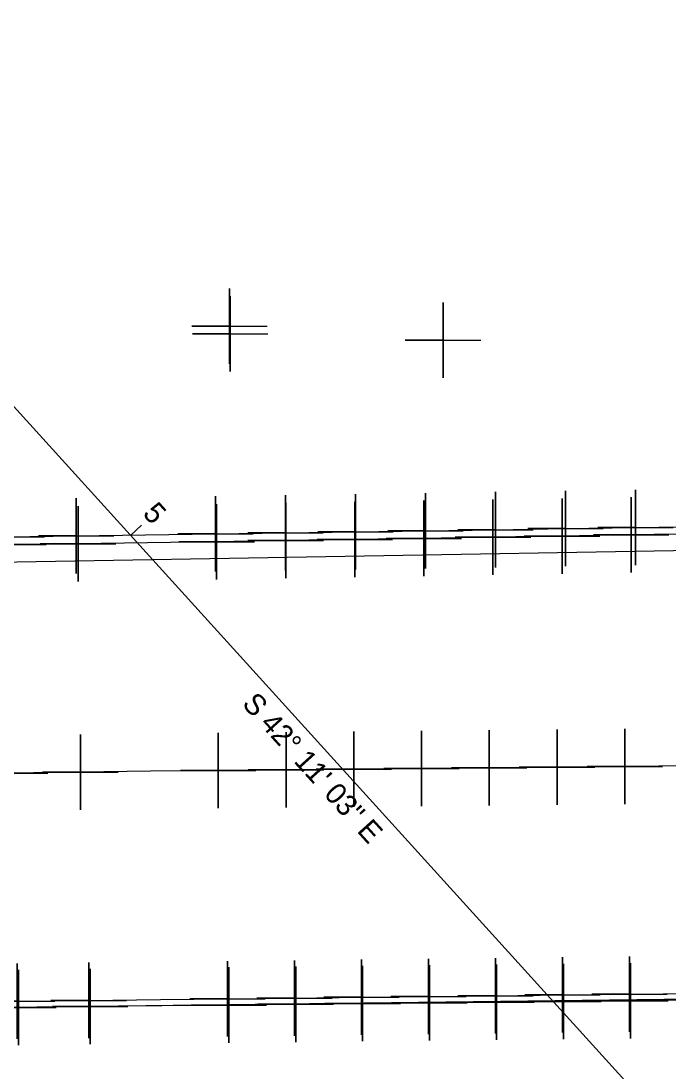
# Model space of a CAD drawing. Extents: x 2260968 to 2264340, y 653057 to 655850.
# Drawn here: x 2261593.4 to 2261636.4, y 655221.5 to 655291.1 of the extents above; entities that cross this region are included whole.
import ezdxf

# ---------------------------------------------------------------- set-up
doc = ezdxf.new("R2010")
doc.units = 0
for name, color, linetype in [('CL_X_Construction', 7, 'Continuous'), ('Default', 7, 'Continuous'), ('GE_X_CL_10', 7, 'Continuous'), ('GK_Patterns2', 7, 'Continuous')]:
    doc.layers.add(name, color=color, linetype=linetype)

msp = doc.modelspace()

# ---------------------------------------------------------------- linework, layer by layer
at = {"layer": 'CL_X_Construction'}
msp.add_line((2261565.655, 655295.67), (2261663.661, 655187.525), dxfattribs=at)
msp.add_line((2261565.655, 655295.67), (2261663.661, 655187.525), dxfattribs=at)
at = {"layer": 'Default'}
for points in [[(2261607.263, 655270.862), (2261607.263, 655273.362), (2261607.263, 655270.862), (2261604.763, 655270.862), (2261607.263, 655270.862), (2261607.263, 655268.362), (2261607.263, 655270.862), (2261609.763, 655270.862)], [(2261607.314, 655270.356), (2261607.314, 655272.856), (2261607.314, 655270.356), (2261604.814, 655270.356), (2261607.314, 655270.356), (2261607.314, 655267.856), (2261607.314, 655270.356), (2261609.814, 655270.356)], [(2261621.417, 655269.943), (2261621.417, 655272.443), (2261621.417, 655269.943), (2261618.917, 655269.943), (2261621.417, 655269.943), (2261621.417, 655267.443), (2261621.417, 655269.943), (2261623.917, 655269.943)], [(2261606.334, 655257.09), (2261606.334, 655259.59), (2261606.334, 655257.09), (2261603.834, 655257.09), (2261606.334, 655257.09), (2261606.334, 655254.59), (2261606.334, 655257.09), (2261608.834, 655257.09)], [(2261610.974, 655257.16), (2261610.974, 655259.66), (2261610.974, 655257.16), (2261608.474, 655257.16), (2261610.974, 655257.16), (2261610.974, 655254.66), (2261610.974, 655257.16), (2261613.474, 655257.16)], [(2261615.615, 655257.23), (2261615.615, 655259.73), (2261615.615, 655257.23), (2261613.115, 655257.23), (2261615.615, 655257.23), (2261615.615, 655254.73), (2261615.615, 655257.23), (2261618.115, 655257.23)], [(2261620.256, 655257.301), (2261620.256, 655259.801), (2261620.256, 655257.301), (2261617.756, 655257.301), (2261620.256, 655257.301), (2261620.256, 655254.801), (2261620.256, 655257.301), (2261622.756, 655257.301)], [(2261624.896, 655257.371), (2261624.896, 655259.871), (2261624.896, 655257.371), (2261622.396, 655257.371), (2261624.896, 655257.371), (2261624.896, 655254.871), (2261624.896, 655257.371), (2261627.396, 655257.371)], [(2261629.537, 655257.441), (2261629.537, 655259.941), (2261629.537, 655257.441), (2261627.037, 655257.441), (2261629.537, 655257.441), (2261629.537, 655254.941), (2261629.537, 655257.441), (2261632.037, 655257.441)], [(2261634.178, 655257.511), (2261634.178, 655260.011), (2261634.178, 655257.511), (2261631.678, 655257.511), (2261634.178, 655257.511), (2261634.178, 655255.011), (2261634.178, 655257.511), (2261636.678, 655257.511)], [(2261592.515, 655256.905), (2261592.515, 655259.405), (2261592.515, 655256.905), (2261590.015, 655256.905), (2261592.515, 655256.905), (2261592.515, 655254.405), (2261592.515, 655256.905), (2261595.015, 655256.905)], [(2261592.623, 655256.38), (2261592.623, 655258.88), (2261592.623, 655256.38), (2261590.123, 655256.38), (2261592.623, 655256.38), (2261592.623, 655253.88), (2261592.623, 655256.38), (2261595.123, 655256.38)], [(2261597.104, 655256.963), (2261597.104, 655259.463), (2261597.104, 655256.963), (2261594.604, 655256.963), (2261597.104, 655256.963), (2261597.104, 655254.463), (2261597.104, 655256.963), (2261599.604, 655256.963)], [(2261597.23, 655256.436), (2261597.23, 655258.936), (2261597.23, 655256.436), (2261594.73, 655256.436), (2261597.23, 655256.436), (2261597.23, 655253.936), (2261597.23, 655256.436), (2261599.73, 655256.436)], [(2261606.415, 655256.567), (2261606.415, 655259.067), (2261606.415, 655256.567), (2261603.915, 655256.567), (2261606.415, 655256.567), (2261606.415, 655254.067), (2261606.415, 655256.567), (2261608.915, 655256.567)], [(2261610.993, 655256.644), (2261610.993, 655259.144), (2261610.993, 655256.644), (2261608.493, 655256.644), (2261610.993, 655256.644), (2261610.993, 655254.144), (2261610.993, 655256.644), (2261613.493, 655256.644)], [(2261615.571, 655256.72), (2261615.571, 655259.22), (2261615.571, 655256.72), (2261613.071, 655256.72), (2261615.571, 655256.72), (2261615.571, 655254.22), (2261615.571, 655256.72), (2261618.071, 655256.72)], [(2261620.15, 655256.797), (2261620.15, 655259.297), (2261620.15, 655256.797), (2261617.65, 655256.797), (2261620.15, 655256.797), (2261620.15, 655254.297), (2261620.15, 655256.797), (2261622.65, 655256.797)], [(2261624.728, 655256.873), (2261624.728, 655259.373), (2261624.728, 655256.873), (2261622.228, 655256.873), (2261624.728, 655256.873), (2261624.728, 655254.373), (2261624.728, 655256.873), (2261627.228, 655256.873)], [(2261629.306, 655256.95), (2261629.306, 655259.45), (2261629.306, 655256.95), (2261626.806, 655256.95), (2261629.306, 655256.95), (2261629.306, 655254.45), (2261629.306, 655256.95), (2261631.806, 655256.95)], [(2261633.885, 655257.026), (2261633.885, 655259.526), (2261633.885, 655257.026), (2261631.385, 655257.026), (2261633.885, 655257.026), (2261633.885, 655254.526), (2261633.885, 655257.026), (2261636.385, 655257.026)], [(2261592.515, 655256.905), (2261597.104, 655256.963), (2261601.693, 655257.02), (2261606.334, 655257.09), (2261610.974, 655257.16), (2261615.615, 655257.23), (2261620.256, 655257.301), (2261624.896, 655257.371), (2261629.537, 655257.441), (2261634.178, 655257.511), (2261638.819, 655257.581), (2261640.893, 655257.621), (2261645.632, 655257.701), (2261650.372, 655257.78), (2261655.111, 655257.86), (2261659.851, 655257.94), (2261664.591, 655258.02), (2261669.33, 655258.099), (2261671.474, 655258.531), (2261673.501, 655258.63), (2261673.465, 655257.734)], [(2261673.465, 655257.734), (2261671.773, 655257.707), (2261669.048, 655257.591), (2261664.413, 655257.514), (2261659.779, 655257.436), (2261655.144, 655257.359), (2261650.509, 655257.282), (2261645.875, 655257.204), (2261641.24, 655257.127), (2261638.463, 655257.102), (2261633.885, 655257.026), (2261629.306, 655256.95), (2261624.728, 655256.873), (2261620.15, 655256.797), (2261615.571, 655256.72), (2261610.993, 655256.644), (2261606.415, 655256.567), (2261601.836, 655256.491), (2261597.23, 655256.436), (2261592.623, 655256.38)], [(2261592.734, 655241.21), (2261592.734, 655243.71), (2261592.734, 655241.21), (2261590.234, 655241.21), (2261592.734, 655241.21), (2261592.734, 655238.71), (2261592.734, 655241.21), (2261595.234, 655241.21)], [(2261597.383, 655241.282), (2261597.383, 655243.782), (2261597.383, 655241.282), (2261594.883, 655241.282), (2261597.383, 655241.282), (2261597.383, 655238.782), (2261597.383, 655241.282), (2261599.883, 655241.282)], [(2261606.523, 655241.398), (2261606.523, 655243.898), (2261606.523, 655241.398), (2261604.023, 655241.398), (2261606.523, 655241.398), (2261606.523, 655238.898), (2261606.523, 655241.398), (2261609.023, 655241.398)], [(2261611.013, 655241.443), (2261611.013, 655243.943), (2261611.013, 655241.443), (2261608.513, 655241.443), (2261611.013, 655241.443), (2261611.013, 655238.943), (2261611.013, 655241.443), (2261613.513, 655241.443)], [(2261615.503, 655241.488), (2261615.503, 655243.988), (2261615.503, 655241.488), (2261613.003, 655241.488), (2261615.503, 655241.488), (2261615.503, 655238.988), (2261615.503, 655241.488), (2261618.003, 655241.488)], [(2261619.993, 655241.532), (2261619.993, 655244.032), (2261619.993, 655241.532), (2261617.493, 655241.532), (2261619.993, 655241.532), (2261619.993, 655239.032), (2261619.993, 655241.532), (2261622.493, 655241.532)], [(2261624.483, 655241.577), (2261624.483, 655244.077), (2261624.483, 655241.577), (2261621.983, 655241.577), (2261624.483, 655241.577), (2261624.483, 655239.077), (2261624.483, 655241.577), (2261626.983, 655241.577)], [(2261628.973, 655241.622), (2261628.973, 655244.122), (2261628.973, 655241.622), (2261626.473, 655241.622), (2261628.973, 655241.622), (2261628.973, 655239.122), (2261628.973, 655241.622), (2261631.473, 655241.622)], [(2261633.463, 655241.666), (2261633.463, 655244.166), (2261633.463, 655241.666), (2261630.963, 655241.666), (2261633.463, 655241.666), (2261633.463, 655239.166), (2261633.463, 655241.666), (2261635.963, 655241.666)], [(2261680.913, 655242.353), (2261676.281, 655242.273), (2261671.649, 655242.194), (2261666.836, 655242.125), (2261662.022, 655242.056), (2261657.208, 655241.987), (2261652.395, 655241.918), (2261647.581, 655241.849), (2261642.767, 655241.78), (2261637.953, 655241.711), (2261633.463, 655241.666), (2261628.973, 655241.622), (2261624.483, 655241.577), (2261619.993, 655241.532), (2261615.503, 655241.488), (2261611.013, 655241.443), (2261606.523, 655241.398), (2261602.032, 655241.353), (2261597.383, 655241.282), (2261592.734, 655241.21)], [(2261620.456, 655226.406), (2261620.456, 655228.906), (2261620.456, 655226.406), (2261617.956, 655226.406), (2261620.456, 655226.406), (2261620.456, 655223.906), (2261620.456, 655226.406), (2261622.956, 655226.406)], [(2261624.898, 655226.457), (2261624.898, 655228.957), (2261624.898, 655226.457), (2261622.398, 655226.457), (2261624.898, 655226.457), (2261624.898, 655223.957), (2261624.898, 655226.457), (2261627.398, 655226.457)], [(2261629.341, 655226.508), (2261629.341, 655229.008), (2261629.341, 655226.508), (2261626.841, 655226.508), (2261629.341, 655226.508), (2261629.341, 655224.008), (2261629.341, 655226.508), (2261631.841, 655226.508)], [(2261633.784, 655226.559), (2261633.784, 655229.059), (2261633.784, 655226.559), (2261631.284, 655226.559), (2261633.784, 655226.559), (2261633.784, 655224.059), (2261633.784, 655226.559), (2261636.284, 655226.559)], [(2261593.186, 655226.097), (2261593.186, 655228.597), (2261593.186, 655226.097), (2261590.686, 655226.097), (2261593.186, 655226.097), (2261593.186, 655223.597), (2261593.186, 655226.097), (2261595.686, 655226.097)], [(2261597.936, 655226.149), (2261597.936, 655228.649), (2261597.936, 655226.149), (2261595.436, 655226.149), (2261597.936, 655226.149), (2261597.936, 655223.649), (2261597.936, 655226.149), (2261600.436, 655226.149)], [(2261598.031, 655225.733), (2261598.031, 655228.233), (2261598.031, 655225.733), (2261595.531, 655225.733), (2261598.031, 655225.733), (2261598.031, 655223.233), (2261598.031, 655225.733), (2261600.531, 655225.733)], [(2261607.128, 655226.252), (2261607.128, 655228.752), (2261607.128, 655226.252), (2261604.628, 655226.252), (2261607.128, 655226.252), (2261607.128, 655223.752), (2261607.128, 655226.252), (2261609.628, 655226.252)], [(2261607.22, 655225.84), (2261607.22, 655228.34), (2261607.22, 655225.84), (2261604.72, 655225.84), (2261607.22, 655225.84), (2261607.22, 655223.34), (2261607.22, 655225.84), (2261609.72, 655225.84)], [(2261611.571, 655226.303), (2261611.571, 655228.803), (2261611.571, 655226.303), (2261609.071, 655226.303), (2261611.571, 655226.303), (2261611.571, 655223.803), (2261611.571, 655226.303), (2261614.071, 655226.303)], [(2261611.655, 655225.885), (2261611.655, 655228.385), (2261611.655, 655225.885), (2261609.155, 655225.885), (2261611.655, 655225.885), (2261611.655, 655223.385), (2261611.655, 655225.885), (2261614.155, 655225.885)], [(2261616.013, 655226.355), (2261616.013, 655228.855), (2261616.013, 655226.355), (2261613.513, 655226.355), (2261616.013, 655226.355), (2261616.013, 655223.855), (2261616.013, 655226.355), (2261618.513, 655226.355)], [(2261616.091, 655225.931), (2261616.091, 655228.431), (2261616.091, 655225.931), (2261613.591, 655225.931), (2261616.091, 655225.931), (2261616.091, 655223.431), (2261616.091, 655225.931), (2261618.591, 655225.931)], [(2261620.526, 655225.976), (2261620.526, 655228.476), (2261620.526, 655225.976), (2261618.026, 655225.976), (2261620.526, 655225.976), (2261620.526, 655223.476), (2261620.526, 655225.976), (2261623.026, 655225.976)], [(2261624.961, 655226.021), (2261624.961, 655228.521), (2261624.961, 655226.021), (2261622.461, 655226.021), (2261624.961, 655226.021), (2261624.961, 655223.521), (2261624.961, 655226.021), (2261627.461, 655226.021)], [(2261629.397, 655226.066), (2261629.397, 655228.566), (2261629.397, 655226.066), (2261626.897, 655226.066), (2261629.397, 655226.066), (2261629.397, 655223.566), (2261629.397, 655226.066), (2261631.897, 655226.066)], [(2261633.832, 655226.111), (2261633.832, 655228.611), (2261633.832, 655226.111), (2261631.332, 655226.111), (2261633.832, 655226.111), (2261633.832, 655223.611), (2261633.832, 655226.111), (2261636.332, 655226.111)], [(2261593.278, 655225.672), (2261593.278, 655228.172), (2261593.278, 655225.672), (2261590.778, 655225.672), (2261593.278, 655225.672), (2261593.278, 655223.172), (2261593.278, 655225.672), (2261595.778, 655225.672)], [(2261593.186, 655226.097), (2261597.936, 655226.149), (2261602.686, 655226.201), (2261607.128, 655226.252), (2261611.571, 655226.303), (2261616.013, 655226.355), (2261620.456, 655226.406), (2261624.898, 655226.457), (2261629.341, 655226.508), (2261633.784, 655226.559), (2261638.226, 655226.611), (2261643.115, 655226.651), (2261648.003, 655226.691), (2261652.892, 655226.732), (2261657.781, 655226.772), (2261662.669, 655226.812), (2261667.558, 655226.853), (2261672.446, 655226.893), (2261675.22, 655226.873), (2261679.475, 655226.946)], [(2261593.186, 655226.097), (2261597.936, 655226.149), (2261602.686, 655226.201), (2261607.128, 655226.252), (2261611.571, 655226.303), (2261616.013, 655226.355), (2261620.456, 655226.406), (2261624.898, 655226.457), (2261629.341, 655226.508), (2261633.784, 655226.559), (2261638.226, 655226.611), (2261643.115, 655226.651), (2261648.003, 655226.691), (2261652.892, 655226.732), (2261657.781, 655226.772), (2261662.669, 655226.812), (2261667.558, 655226.853), (2261672.446, 655226.893), (2261675.22, 655226.873), (2261679.475, 655226.946)], [(2261679.252, 655226.412), (2261674.974, 655226.328), (2261672.793, 655226.326), (2261667.861, 655226.302), (2261662.929, 655226.277), (2261657.996, 655226.253), (2261653.064, 655226.229), (2261648.132, 655226.205), (2261643.2, 655226.181), (2261638.268, 655226.156), (2261633.832, 655226.111), (2261629.397, 655226.066), (2261624.961, 655226.021), (2261620.526, 655225.976), (2261616.091, 655225.931), (2261611.655, 655225.885), (2261607.22, 655225.84), (2261602.785, 655225.795), (2261598.031, 655225.733), (2261593.278, 655225.672)], [(2261679.252, 655226.412), (2261674.974, 655226.328), (2261672.793, 655226.326), (2261667.861, 655226.302), (2261662.929, 655226.277), (2261657.996, 655226.253), (2261653.064, 655226.229), (2261648.132, 655226.205), (2261643.2, 655226.181), (2261638.268, 655226.156), (2261633.832, 655226.111), (2261629.397, 655226.066), (2261624.961, 655226.021), (2261620.526, 655225.976), (2261616.091, 655225.931), (2261611.655, 655225.885), (2261607.22, 655225.84), (2261602.785, 655225.795), (2261598.031, 655225.733), (2261593.278, 655225.672)]]:
    msp.add_lwpolyline(points, dxfattribs=at)
at = {"layer": 'GE_X_CL_10'}
for p, q in [((2261565.655, 655295.67), (2261663.661, 655187.525)), ((2261600.704, 655256.995), (2261601.445, 655257.666)), ((2261600.704, 655256.995), (2261601.445, 655257.666))]:
    msp.add_line(p, q, dxfattribs=at)
at = {"layer": 'GK_Patterns2'}
msp.add_line((2261355.086, 655251.133), (2262026.124, 655262.728), dxfattribs=at)
msp.add_lwpolyline([(2261345.094, 655222.664), (2261872.81, 655229.12), (2261952.63, 655230.755), (2261996.16, 655231.647), (2261996.16, 655231.647)], dxfattribs=at)

# ---------------------------------------------------------------- texts
at = {"layer": 'GE_X_CL_10'}
for s, p in [('5', (2261601.456, 655258.398)), ('5', (2261601.456, 655258.398)), ('S 42%%d 11\' 03" E', (2261608.039, 655245.773))]:
    msp.add_text(s, height=1.4, rotation=312.18426, dxfattribs=at).set_placement(p)

doc.saveas('drawing.dxf')
